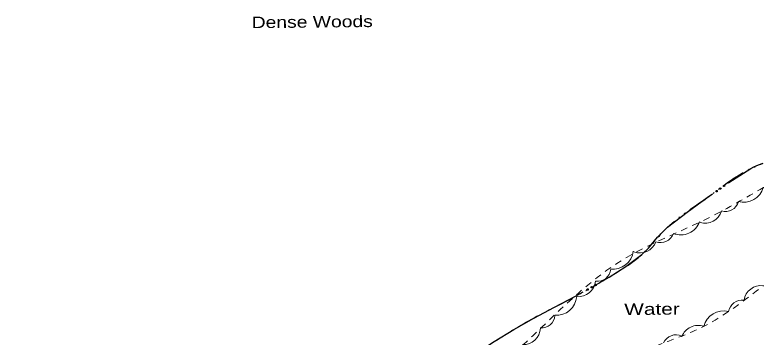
# Model space of a CAD drawing. Extents: x 2362213 to 2366494, y 6968794 to 6978110.
# Drawn here: x 2364707.7 to 2365019.3, y 6970819.7 to 6970953.7 of the extents above; entities that cross this region are included whole.
import ezdxf

# ---------------------------------------------------------------- set-up
doc = ezdxf.new("R2010")
doc.units = 0
doc.header["$LTSCALE"] = 1.9
doc.linetypes.add('DASH_DOUBLE_DOT', pattern=[9.2, 5, -1.2, 0.3, -1.2, 0.3, -1.2])
doc.linetypes.add('SHORT_DASHED', pattern=[2.7, 1.5, -1.2])
doc.layers.add('25', color=7, linetype='Continuous', lineweight=25)
doc.layers.add('29', color=7, linetype='Continuous', lineweight=13)

msp = doc.modelspace()

# ---------------------------------------------------------------- linework, layer by layer
at = {"layer": '25'}
for points in [[(2365004.362, 6970883.7), (2365004.7, 6970883.933), (2365013.905, 6970889.852), (2365015.119, 6970890.514), (2365017.011, 6970891.312), (2365018.985, 6970892.011)], [(2364950.964, 6970842.351), (2364954.922, 6970844.648), (2364961.871, 6970849.094), (2364968.474, 6970854.037), (2364971.289, 6970856.724), (2364975.075, 6970861.21), (2364979.176, 6970865.36), (2364987.357, 6970871.649), (2364995.73, 6970877.708), (2364997.925, 6970879.229)], [(2364892.234, 6970808.469), (2364893.735, 6970809.373), (2364900.397, 6970813.567), (2364907.046, 6970817.76), (2364915.229, 6970822.75), (2364923.514, 6970827.568), (2364932.16, 6970832.15), (2364940.859, 6970836.643), (2364944.151, 6970838.475)]]:
    msp.add_lwpolyline(points, dxfattribs=at)
for centre in [(2364999.579, 6970880.38), (2365001.157, 6970881.475), (2365002.734, 6970882.569), (2364947.58, 6970840.391), (2364949.244, 6970841.35), (2364945.903, 6970839.456)]:
    msp.add_circle(centre, 0.3, dxfattribs=at)
at = {"layer": '25', "linetype": 'DASH_DOUBLE_DOT'}
msp.add_spline([(2364482.891, 6970556.82), (2364489.199, 6970561.15), (2364517.788, 6970579.273), (2364539.624, 6970595.541), (2364563.069, 6970609.905), (2364584.89, 6970623.464), (2364602.365, 6970632.611), (2364621.28, 6970642.711), (2364636.603, 6970653.948), (2364651.424, 6970666.489), (2364670.773, 6970681.414), (2364691.29, 6970695.5), (2364705.308, 6970706.304), (2364720.102, 6970713.305), (2364729.676, 6970717.157), (2364739.325, 6970717.339), (2364750.211, 6970717.802), (2364763.262, 6970717.797), (2364791.192, 6970716.793), (2364812.303, 6970724.174), (2364826.243, 6970733.617), (2364838.787, 6970747.007), (2364842.06, 6970754.03), (2364841.565, 6970758.714), (2364836.228, 6970762.554), (2364832.89, 6970765.662), (2364835.307, 6970769.025), (2364848.712, 6970783.223), (2364860.811, 6970790.739), (2364877.348, 6970799.678), (2364893.735, 6970809.373), (2364907.046, 6970817.76), (2364923.514, 6970827.568), (2364940.859, 6970836.643), (2364954.922, 6970844.648), (2364968.474, 6970854.037), (2364979.176, 6970865.36), (2364995.73, 6970877.708), (2365013.905, 6970889.852), (2365018.985, 6970892.011)], degree=3, dxfattribs=at)
at = {"layer": '29'}
for centre, radius, start, end in [((2365010.856, 6970884.267), 8.534, 254.5494, 344.5494), ((2365003.241, 6970877.592), 5.686, 253.60571, 343.60571), ((2364994.789, 6970874.13), 7.115, 253.60571, 343.60571), ((2364984.606, 6970870.709), 8.534, 249.27433, 339.27433), ((2364976.344, 6970864.674), 5.686, 249.69684, 339.69684), ((2364967.676, 6970861.796), 7.115, 249.69684, 339.69684), ((2364956.448, 6970856.399), 8.534, 263.42645, 353.42645), ((2364949.934, 6970848.547), 5.686, 263.42645, 353.42645), ((2364942.198, 6970843.694), 7.115, 263.42645, 353.42645), ((2365018.061, 6970833.999), 7.092, 82.02241, 172.02241), ((2364932.905, 6970837.227), 8.534, 265.64834, 355.64834), ((2365010.233, 6970829.352), 5.668, 82.02241, 172.02241), ((2364926.701, 6970829.128), 5.686, 265.64834, 355.64834), ((2365002.569, 6970822.075), 8.506, 76.44239, 166.44239), ((2364991.895, 6970817.447), 7.092, 70.51225, 160.51225), ((2364919.224, 6970823.66), 7.115, 267.50325, 357.50325), ((2364982.771, 6970814.961), 5.668, 66.44192, 156.44192)]:
    msp.add_arc(centre, radius, start, end, dxfattribs=at)
at = {"layer": '29', "linetype": 'SHORT_DASHED'}
for points in [[(2365019.121, 6970881.93), (2364996.688, 6970869.457), (2364960.276, 6970851.639), (2364929.02, 6970825.84), (2364896.367, 6970797.759), (2364866.083, 6970780.039), (2364824.589, 6970756.132), (2364789.579, 6970751.739), (2364758.069, 6970732.678), (2364744.059, 6970703.253), (2364731.347, 6970677.121), (2364705.16, 6970657.801), (2364666.248, 6970645.26), (2364623.645, 6970656.834), (2364578.525, 6970639.873), (2364554.47, 6970611.914), (2364537.05, 6970588.597), (2364522.908, 6970574.22), (2364506.784, 6970570.287), (2364482.866, 6970573.149)], [(2365019.344, 6970741.976), (2365013.583, 6970748.262), (2365003.35, 6970744.224), (2364989.177, 6970735.179), (2364981.124, 6970725.912), (2364978.952, 6970711.4), (2364989.669, 6970697.142), (2365002.522, 6970686.285), (2365003.085, 6970672.298), (2364993.278, 6970662.614), (2364980.234, 6970648.13), (2364962.83, 6970612.932), (2364946.985, 6970580.76), (2364933.414, 6970542.959), (2364930.334, 6970505.147), (2364923.417, 6970477.53), (2364897.761, 6970466.516), (2364866.188, 6970470.776), (2364836.123, 6970473.349), (2364795.817, 6970475.796), (2364767.656, 6970480.077), (2364748.092, 6970503.421), (2364708.874, 6970477.837), (2364679.431, 6970464.306), (2364646.865, 6970444.886), (2364624.431, 6970430.481), (2364612.969, 6970400.141), (2364604.826, 6970354.251), (2364605.553, 6970317.806), (2364606.592, 6970290.644), (2364601.528, 6970267.945), (2364588.81, 6970268.694), (2364579.544, 6970276.606), (2364580.363, 6970312.406), (2364581.871, 6970360.932), (2364581.995, 6970404.655), (2364573.318, 6970428.424), (2364549.103, 6970435.154), (2364543.286, 6970441.098), (2364535.306, 6970454.743), (2364525.155, 6970470.518), (2364519.677, 6970490.277), (2364530.681, 6970517.193), (2364547.703, 6970543.275), (2364568.076, 6970553.571), (2364584.707, 6970547.148), (2364614.664, 6970561.425), (2364638.924, 6970579.316), (2364671.914, 6970607.812), (2364684.38, 6970620.921), (2364713.797, 6970629.752), (2364754.136, 6970656.387), (2364756.635, 6970676.392), (2364760.896, 6970685.742), (2364783.651, 6970704.25), (2364813.03, 6970713.99), (2364839.877, 6970707.106), (2364862.329, 6970704.859), (2364897.161, 6970715.382), (2364909.564, 6970730.761), (2364927.94, 6970754.397), (2364941.131, 6970774.483), (2364947.076, 6970797.082), (2364974.605, 6970816.044), (2364994.111, 6970824.041), (2365019.18, 6970841.1)]]:
    msp.add_spline(points, degree=3, dxfattribs=at)

# ---------------------------------------------------------------- texts
at = {"layer": '25', "width": 1.35}
msp.add_text('Water', height=4.8, rotation=0.546, dxfattribs=at).set_placement((2364961.193, 6970828.816))
at = {"layer": '29', "width": 1.25}
msp.add_text('Dense Woods', height=4.8, rotation=0.546, dxfattribs=at).set_placement((2364806.199, 6970948.216))

doc.saveas('drawing.dxf')
